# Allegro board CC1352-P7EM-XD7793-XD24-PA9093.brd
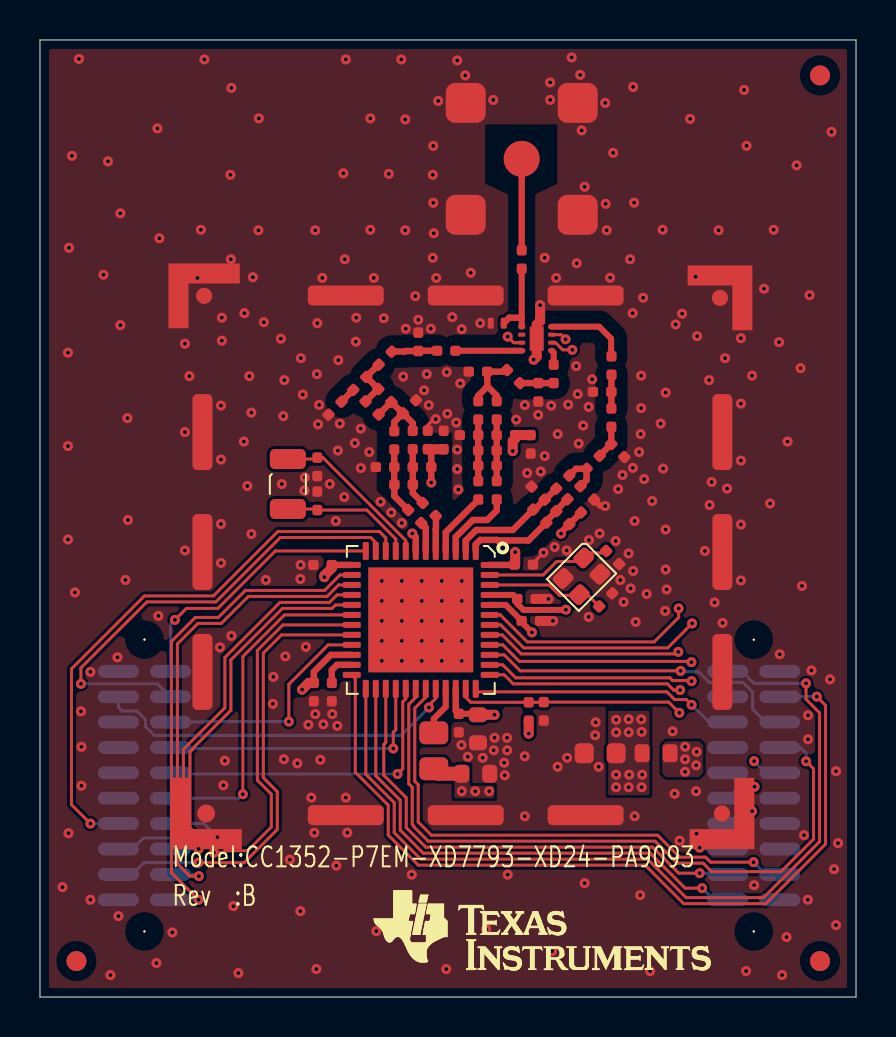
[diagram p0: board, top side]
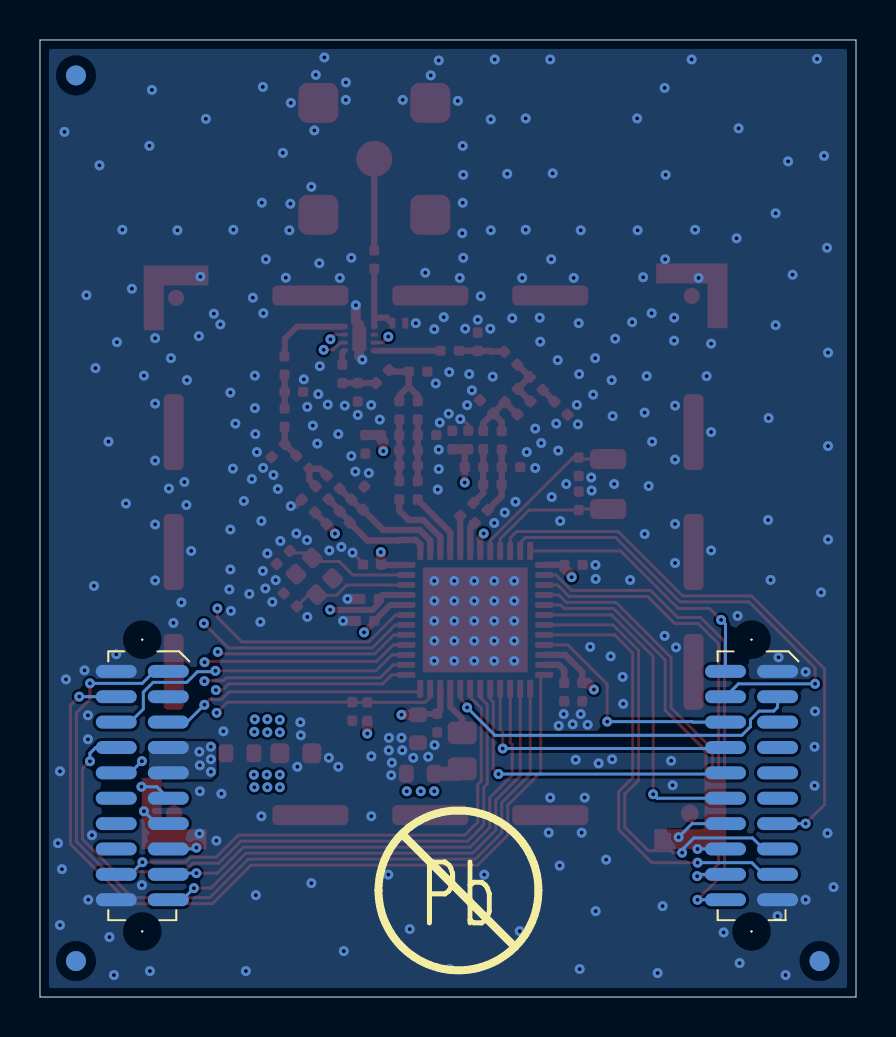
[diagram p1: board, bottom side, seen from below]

Outline 40.83 x 47.9 mm; copper layers: TOP, L2, L3, BOTTOM. Coordinates in mm from the lower left corner of the outline.
Outline path: 0,47.9 0,0 40.83,0 40.83,47.9 0,47.9

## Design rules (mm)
constraint set DEFAULT: min track width 0.15
net group RF SPACING: nets N485531 N485663 N485827 N485903 N512033 N512042 N512564 N513741 N516755 N517801 N517942 N518069 N553230 N583481 N2475926 N2476223 N2476600 N5175910

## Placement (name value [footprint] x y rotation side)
C1  22uF  [CAPC1608X100A2N#2]  28.83 12.2 180 top
C11  12pF  [CAPC1005X60B2N]  27.06 24.25 45 top
C12  1.1pF  [CAPC1005X60B2N]  26.39 24.91 45 top
C13  1pF  [CAPC1005X60B2N]  28.58 27.68 315 top
C14  1pF  [CAPC1005X60B2N]  28.58 30.29 180 top
C15  12pF  [CAPC1005X60B2N]  28.59 31.14 90 top
C21  1.1pF  [CAPC1005X60B2N]  25.25 24.89 135 top
C31  1.2pF  [CAPC1005X60B2N]  22.85 26.6 180 top
C32  100pF  [CAPC1005X60B2N]  24.55 28.12 270 top
C33  3pF  [CAPC1005X60B2N]  22.85 28.9 90 top
C34  2.7pF  [CAPC1005X60B2N]  22.37 31.3 180 top
C35  5.6pF  [CAPC1005X60B2N]  24.93 30.73 270 top
C37  100pF  [CAPC1005X60B2N]  25.7 31.65 270 top
C41  3pF  [CAPC1005X60B2N]  21.92 28.12 180 top
C51  82pF  [CAPC1005X60B2N]  19.4 28.35 270 top
C52  10nF  [CAPC1005X60B2N]  20.2 27.41 90 top
C53  2.4pF  [CAPC1005X60B2N]  18.65 27.41 90 top
C54  3.9pF  [CAPC1005X60B2N]  18.16 29.22 45 top
C55  0.7pF  [CAPC1005X60B2N]  16.94 29.16 135 top
C56  2.7pF  [CAPC1005X60B2N]  16.33 31.04 225 top
C57  2.7pF  [CAPC1005X60B2N]  18.93 32.33 90 top
C58  82pF  [CAPC1005X60B2N]  19.86 32.34 0 top
C61  2.4pF  [CAPC1005X60B2N]  16.8 26.52 0 top
C81  12pF  [CAPC1005X60B2N]  13.88 27 270 top
C91  12pF  [CAPC1005X60B2N]  13.88 24.38 90 top
C131  0.1uF  [CAPC1005X60B2N]  14.6 21.62 180 top
C221  0.1uF  [CAPC1005X60B2N]  13.7 15.72 270 top
C231  1uF  [CAPC1005X60B2N]  14.6 15.72 270 top
C331  22uF  [CAPC1608X100A2N]  21.1 11.17 0 top
C341  22uF  [CAPC1608X100A2N]  21.91 14.13 270 top
C342  0.1uF  [CAPC1005X60B2N]  20.95 14.17 270 top
C351  0.1uF  [CAPC1005X60B2N]  25.2 14.76 270 top
C441  0.1uF  [CAPC1005X60B2N]  24.1 18.83 0 top
C451  0.1uF  [CAPC1005X60B2N]  23.87 19.92 0 top
C461  7.5pF  [CAPC1005X60B2N]  27.98 19.55 45 top
C471  7.5pF  [CAPC1005X60B2N]  28.33 22.33 315 top
C481  0.1uF  [CAPC1005X60B2N]  23.74 21.64 0 top
C482  100pF  [CAPC1005X60B2N]  24.1 36.45 90 top
CR13  TPD1E0B04DPY  [SON65P100X60X45-2A2N]  22.55 33.72 0 top
FIDU1  FIDU_1MM  [FID100X115B]  1.83 1.8 0 top
FIDU2  FIDU_1MM  [FID100X115B]  39.02 1.8 0 top
FIDU3  FIDU_1MM  [FID100X115B]  39.02 46.12 0 top
FIDU4  FIDU_1MM  [FID100X115B]  1.83 1.8 180 bottom
FIDU5  FIDU_1MM  [FID100X115B]  39.02 1.8 180 bottom
FIDU6  FIDU_1MM  [FID100X115B]  39.02 46.12 180 bottom
FL1  BLM18HE152SN1  [FIL_BLM18HE152SN1DN]  30.12 12.2 0 top
J1  SMA-10V21-TGG  [HUSTSAN_SMA10V21TGGAN]  24.1 41.95 0 top
L11  15nH  [INDC1005X60D2N]  25.33 23.75 135 top
L12  2.4nH  [INDC1005X60D2N]  25.83 24.32 315 top
L13  1.5nH  [INDC1005X60D2N]  27.35 26.44 45 top
L14  2nH  [INDC1005X60D2N]  28.59 28.53 90 top
L21  2.4nH  [INDC1005X60D2N]  25.83 25.45 45 top
L31  3.9nH  [INDC1005X60D2N]  22.85 24.9 90 top
L32  22nH  [INDC1005X60D2N]  22.85 27.35 180 top
L33  10nH  [INDC1005X60D2N]  23.77 28.12 180 top
L34  7.5nH  [INDC1005X60D2N]  23.36 31.38 315 top
L41  3.9nH  [INDC1005X60D2N]  21.93 24.9 90 top
L42  10nH  [INDC1005X60D2N]  21.92 28.9 90 top
L51  1nH  [INDC1005X60D2N]  19.8 24.08 135 top
L52  27nH  [INDC1005X60D2N]  18.65 25.65 180 top
L53  12nH  [INDC1005X60B2N]  19.58 26.52 180 top
L54  4.3nH  [INDC1005X60B2N]  17.58 29.78 135 top
L55  2.5nH  [INDC1005X60B2N]  15.09 29.8 225 top
L56  4.7nH  [INDC1005X60B2N]  16.94 31.65 45 top
L61  1nH  [INDC1005X60D2N]  19.08 23.72 135 top
L62  12nH  [INDC1005X60B2N]  17.72 27.4 90 top
L331  6.8uH  [INDC2012X150A2N]  19.7 13.22 270 top
LBL1  TI_LOGO  [TI_LOGO_1]  17.67 5.35 0 top
LBL2  NON_COMPONENT_LABEL_8mm  [LABEL_PB-FREE_8MM_A2N]  24.1 1.12 180 bottom
NOREF  -  []  38.57 0 90 top
NOREF#2  -  []  0 42.03 0 top
P1  SFM-110-02-S-D-A-K  [SAMTEC_SFM11002AN]  3.92 16.3 0 bottom
P2  SFM-110-02-S-D-A-K  [SAMTEC_SFM11002AN]  34.4 16.3 0 bottom
R351  100k  [RESC1005X40B2N]  24.45 14.75 270 top
SC1  BMI-S-203-F  [MECH_BMIS203_A2N]  8.41 9.09 0 top
SC2  BMIS-203-C  [MECH_BMIS203C]  7.92 8.67 0 top
U1  CC1352P1F64TRGZ  [QFNFC50P700X700X100-49A2N]  21.8 22.33 180 top
U2  SKY13317-373  [SON40P150X150X50-9A2N]  24.1 33.55 270 top
Y1  32.768kHz  [XTAL_TZ1166C_A2N]  12.4 26.92 270 top
Y2  48MHz  [OSCCC200X160X50-4A2N]  27.2 21.97 225 top

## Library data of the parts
C1 C331 C341 = CAPACITOR: User Part Number: #PN; alternate symbols: (CAPC1608X100A2L,CAPC1608X100A2M)
C11-C15 C21 C31-C35 C37 C41 C51-C58 C61 C81 C91 C131 C221 C231 C342 C351 C441 C451 C461 C471 C481 C482 = CAPACITOR: User Part Number: #PN
CR13 = DIODE_TVS_BIDIR_S: User Part Number: #PN
FIDU1-FIDU6 = FIDMARK
FL1 = FILTER_2PIN: alternate symbols: (FIL_BLM18HE152SN1DL,FIL_BLM18HE152SN1DM)
J1 = CONN_COAX_1+4: alternate symbols: (HUSTSAN_SMA10V21TGGL,HUSTSAN_SMA10V21TGGM)
L11 L31 L33 L41 L42 L51 L61 = INDUCTOR_HOR_1_2: User Part Number: #PN; alternate symbols: (INDC1005X60C2L,INDC1005X60C2M)
L12-L14 L21 L32 L34 L52 = INDUCTOR_HOR_1_2: User Part Number: #PN
L53-L56 L62 = INDUCTOR: User Part Number: #PN; alternate symbols: (INDC1005X60A2L,INDC1005X60A2M)
L331 = INDUCTOR: User Part Number: #PN; alternate symbols: (INDC2012X150A2L,INDC2012X150A2M)
LBL1 = TI_LOGO_V1
LBL2 = LABEL_Pb-free_V1: User Part Number: #PN
P1 P2 = CONN_HEADER_2X10_P_S: alternate symbols: (SAMTEC_SFM11002AL,SAMTEC_SFM11002AM)
R351 = RESISTOR: User Part Number: #PN
SC1 = SHIELD_COVER_BMIS-203
SC2 = SHIELD_COVER: User Part Number: #PN
U1 = IC_RF_CC1352P1F64_QFN48: User Part Number: #PN; alternate symbols: (QFNFC50P700X700X100-49A2L,QFNFC50P700X700X100-49A2M)
U2 = IC_RF_SKY13317-373LF_MLP8: User Part Number: #PN
Y1 = XTAL: User Part Number: #PN; alternate symbols: (XTAL_TZ1166C_A2L,XTAL_TZ1166C_A2M)
Y2 = XTAL_4_V3: User Part Number: #PN; alternate symbols: (OSCCC200X160X50-4A2L,OSCCC200X160X50-4A2M)

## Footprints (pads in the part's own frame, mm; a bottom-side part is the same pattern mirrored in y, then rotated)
CAPC1005X60B2N
  custom 0.125x0.125 smd: 1(0,0) 2(0.924,0)
CAPC1608X100A2N
  custom 0.188x0.188 smd: 1(0,0) 2(1.4,0)
CAPC1608X100A2N#2
  custom 0.237x0.237 smd: 1(0,0) 2(1.6,0)
FID100X115B
  round 1 smd: 1(0,0)
FIL_BLM18HE152SN1DN
  custom 0.188x0.188 smd: 1(0,0) 2(1.4,0)
HUSTSAN_SMA10V21TGGAN
  round 1.801 smd: 1(0,0)
  custom 0.5x0.5 smd: 2(-2.8,-2.8) 3(2.8,-2.8) 4(2.8,2.8) 5(-2.8,2.8)
INDC1005X60B2N
  custom 0.125x0.125 smd: 1(0,0) 2(0.924,0)
INDC1005X60D2N
  custom 0.125x0.125 smd: 1(0,0) 2(0.924,0)
INDC2012X150A2N
  custom 0.287x0.287 smd: 1(0,0) 2(1.8,0)
MECH_BMIS203_A2N
  custom 0.892x0.892 smd: 1(-0.1,0.1)
  custom 0.25x0.25 smd: 2(6.885,0.015) 3(12.885,0.015) 4(18.885,0.015) 6(25.725,7.185) 7(25.725,13.185) 8(25.725,19.185) 10(18.885,26.025) 11(12.885,26.025) 12(6.885,26.025) 14(-0.285,19.185) 15(-0.285,13.185) 16(-0.285,7.185)
  custom 0.81x0.81 smd: 5(25.705,0.1) 9(25.605,25.905) 13(-0.2,26.005)
OSCCC200X160X50-4A2N
  custom 0.2x0.2 smd: 1(0,0) 2(1.45,0) 3(1.45,1.15) 4(0,1.15)
QFNFC50P700X700X100-49A2N
  custom 0.075x0.075 smd: 1(0,0) 2(0.5,0) 3(1,0) 4(1.5,0) 5(2,0) 6(2.5,0) 7(3,0) 8(3.5,0) 9(4,0) 10(4.5,0) 11(5,0) 12(5.5,0) 13(6.2,0.7) 14(6.2,1.2) 15(6.2,1.7) 16(6.2,2.2) 17(6.2,2.7) 18(6.2,3.2) 19(6.2,3.7) 20(6.2,4.2) 21(6.2,4.7) 22(6.2,5.2) 23(6.2,5.7) 24(6.2,6.2) 25(5.5,6.9) 26(5,6.9) 27(4.5,6.9) 28(4,6.9) 29(3.5,6.9) 30(3,6.9) 31(2.5,6.9) 32(2,6.9) 33(1.5,6.9) 34(1,6.9) 35(0.5,6.9) 36(0,6.9) 37(-0.7,6.2) 38(-0.7,5.7) 39(-0.7,5.2) 40(-0.7,4.7) 41(-0.7,4.2) 42(-0.7,3.7) 43(-0.7,3.2) 44(-0.7,2.7) 45(-0.7,2.2) 46(-0.7,1.7) 47(-0.7,1.2) 48(-0.7,0.7)
  rect 5.25x5.25 smd: 49(2.75,3.45)
RESC1005X40B2N
  custom 0.125x0.125 smd: 1(0,0) 2(0.924,0)
SAMTEC_SFM11002AN
  round 0.099 hole 1.501 unplated: (1.302,-1.588) (1.302,13.017)
  oval 2.05x0.65 smd: 1(0,0) 2(2.604,0) 3(0,1.27) 4(2.604,1.27) 5(0,2.54) 6(2.604,2.54) 7(0,3.81) 8(2.604,3.81) 9(0,5.08) 10(2.604,5.08) 11(0,6.35) 12(2.604,6.35) 13(0,7.62) 14(2.604,7.62) 15(0,8.89) 16(2.604,8.89) 17(0,10.16) 18(2.604,10.16) 19(0,11.43) 20(2.604,11.43)
SON40P150X150X50-9A2N
  custom 0.05x0.05 smd: 1(0,0) 2(0.4,0) 3(0.8,0) 4(1.2,0) 5(1.2,1.5) 6(0.8,1.5) 7(0.4,1.5) 8(0,1.5)
  rect 1.2x0.7 smd: 9(0.6,0.75)
SON65P100X60X45-2A2N
  custom 0.075x0.075 smd: 1(0,0) 2(0.65,0)
XTAL_TZ1166C_A2N
  custom 0.25x0.25 smd: 1(0,0) 2(2.5,0)

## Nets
GND: C1.2 C11.2 C13.2 C14.2 C21.2 C32.2 C34.2 C35.2 C41.2 C51.1 C52.2 C54.2 C57.2 C61.1 C81.2 C91.2 C131.2 C221.2 C231.2 C331.2 C341.2 C342.2 C351.2 C441.2 C451.2 C461.2 C471.2 C481.2 CR13.1 J1.2 J1.3 J1.4 J1.5 L55.2 P1.1 P1.19 P2.2 P2.20 SC1.1 SC1.2 SC1.3 SC1.4 SC1.5 SC1.6 SC1.7 SC1.8 SC1.9(GND#9) SC1.10 SC1.11 SC1.12 SC1.13 SC1.14 SC1.15 SC1.16 U1.49 U2.9 Y2.2 Y2.4(GND#4)
VDD_EB: FL1.2 P2.7 P2.9
VDDR: C331.1 C451.1 C481.1 L331.2 U1.45 U1.48
VDDS: C1.1 C51.2 C52.1 C131.1 C221.1 C341.1 C342.1 C441.1 FL1.1 L53.1 R351.2 U1.13 U1.22 U1.34 U1.44
DCDC_SW: L331.1 U1.33
DIO_5: P1.13 U1.10
DIO_6: P1.4 U1.11
DIO_7: P1.2 U1.12
DIO_8: P1.20 U1.14
DIO_9: P1.18 U1.15(DIO_9)
DIO_10: P1.16 U1.16
DIO_11: P1.14 U1.17
DIO_12: P1.12 U1.18
DIO_13: P1.15 U1.19
DIO_14: P1.17 U1.20
DIO_15: P1.6 U1.21
DIO_16 / JTAG TDO: P2.19 U1.26
DIO_17 / JTAG TDI: P2.17 U1.27
DIO_18: P1.8 U1.28
DIO_19: P1.10 U1.29
DIO_20: P2.8 U1.30
DIO_21: P2.18 U1.31
DIO_22: P1.3 U1.32
DIO_23: P2.5 U1.36
DIO_24: P2.10 U1.37
DIO_25: P2.11 U1.38
DIO_26: P2.6 U1.39
DIO_27: P2.13 U1.40
DIO_28: U1.41 U2.7(V3)
DIO_29: U1.42 U2.3
DIO_30: U1.43 U2.6
JTAG_TCK: P2.1 U1.25
JTAG_TMS: P2.4 U1.24
NRESET: C351.1 P2.15 R351.1 U1.35
RX_TX: C11.1 C32.1 L12.2 L33.1 U1.7
N485531: C37.1 U2.5
N485533: C482.2 J1.1
N485663: C33.2 C34.1 L34.1 L42.2
N485699: C231.1 U1.23
N485701: C81.1 U1.8 Y1.1
N485707: C91.1 U1.9 Y1.2
N485827: C35.1 C37.2 L34.2
N485903: C31.1 C33.1 L31.2 L32.1 L33.2
N501959: C471.1 U1.47 Y2.1
N501977: C461.1 U1.46 Y2.3
N512033: C12.2 L13.1 L21.2
N512042: C13.1 L13.2 L14.1
N512564: C15.2 U2.8
N513741: C21.1 L11.2 L21.1 U1.2
N516755: C31.2 C41.1 L32.2 L41.2 L42.1
N517773: C53.1 L51.2 L52.1 L53.2
N517777: C61.2 L52.2 L61.2 L62.1
N517801: C53.2 C54.1 C55.1 L54.1 L62.2
N517942: C55.2 C56.1 L54.2 L56.1
N518069: C57.1 C58.1 L56.2
N553230: C14.1 C15.1 L14.2
N561899: L61.1 U1.6
N583447: C482.1 CR13.2 U2.1
N583481: C58.2 U2.4
N2475876: L51.1 U1.5
N2475926: L41.1 U1.4
N2476223: L31.1 U1.3
N2476600: C12.1 L11.1 L12.1 U1.1
N5175910: C56.2 L55.1

Pads without a net: FIDU1 1; FIDU2 1; FIDU3 1; FIDU4 1; FIDU5 1; FIDU6 1; P1 5 7 9 11; P2 3 12 14 16; U2 2

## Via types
v1: diameter 0.5, hole 0.2, TOP to BOTTOM, 395 vias

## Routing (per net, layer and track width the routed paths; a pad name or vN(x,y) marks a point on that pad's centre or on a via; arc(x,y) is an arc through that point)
GND: length 6.5
  TOP w0.15: C481.2 24.66,21.72 v1(25.19,22.24) ; 19.83,28.92 v1(19.8,28.92) 19.7,28.92 19.4,28.62 C51.1
  TOP w0.3: v1(28.28,24.57) 28.05,24.57 27.72,24.9
  TOP w0.5: C451.2 v1(25.44,19.92) ; v1(25.02,34.62) 25.02,33.82 24.85,33.65 U2.9 24.85,32.05 v1(24.7,31.9) ; C441.2 v1(25.66,18.83) ; 13.23,25.35 v1(13.23,25.35)
  vias: v1(1.12,5.5) v1(1.45,37.5) v1(1.4,32.25) v1(1.4,27.58) v1(1.4,22.9) v1(1.42,8.2) v1(1.6,42.1) v1(1.75,20.25) v1(1.95,46.95) v1(2.05,14.3) v1(2.08,12.52) v1(2.08,10.58) v1(2.52,16.27) v1(2.52,4.87) v1(3.17,36.15) v1(3.4,41.83) v1(3.52,1.1) v1(3.88,17) v1(3.92,4.05) v1(4.02,39.23) v1(4.02,33.62) v1(4.27,20.88) v1(4.38,28.97) v1(4.4,23.88) v1(5.83,1.7) v1(5.88,43.48) v1(5.97,37.98) v1(5.92,19.08) v1(6.62,3.23) v1(7.25,32.7) v1(7.25,28.27) v1(7.25,22.35) v1(7.47,31.08) v1(7.88,35.99) v1(8.05,38.4) v1(8.22,46.92) v1(9.05,29.6) v1(9.05,26.9) v1(9.05,23.67) v1(9.05,21.72) v1(9,17.5) v1(9.1,34) v1(9.1,32.85) v1(9.17,10.6) v1(9.25,11.83) v1(9.52,41.15) v1(9.55,36.92) v1(9.58,45.5) v1(9.58,18.08) v1(9.67,4.55) v1(9.92,1.2) v1(10.22,34.22) v1(10.2,27.8) v1(10.47,31.08) v1(10.38,25.58) v1(10.65,36.02) v1(10.58,29.25) v1(10.58,23.17) v1(10.95,43.98) v1(10.93,38.37) v1(11.2,33.77) v1(11.3,20.88) v1(11.65,14.67) v1(11.67,16.02) v1(12.05,32.95) v1(12.17,29.08) v1(12.1,25.67) v1(12.22,30.88) v1(12.27,17.05) v1(12.2,11.9) v1(12.5,6.88) v1(12.88,11.69) v1(13.05,31.97) v1(13.04,21.62) v1(13.02,20.92) v1(13.02,4.3) v1(13.15,30.15) v1(13.25,26) v1(13.3,17.52) v1(13.42,13.62) v1(13.58,9.98) v1(13.77,38.37) v1(13.77,14.16) v1(13.72,8.23) v1(13.85,31.17) v1(13.83,1.4) v1(13.88,33.72) v1(13.97,29.63) v1(13.91,28.66) v1(14.02,11.88) v1(14.12,35.99) v1(14.17,13.65) v1(14.5,25.67) v1(14.62,14.16) v1(14.8,23.83) v1(14.83,6.58) v1(14.92,31.88) v1(14.9,27.35) v1(14.88,13.58) v1(15,28.7) v1(15.17,41.23) v1(15.25,36.92) v1(15.22,25.02) v1(15.3,46.92) v1(15.3,9.98) v1(15.38,8.23) v1(15.75,27.72) v1(15.82,34) v1(15.8,32.8) v1(16.05,28.45) v1(16.05,26.47) v1(16.47,27.27) v1(16.53,43.98) v1(16.53,38.4) v1(16.7,35.99) v1(16.83,3.3) v1(17.04,24.79) v1(17.1,20.83) v1(17.1,19.83) v1(17.1,18.83) v1(17.1,17.83) v1(17.1,16.83) v1(17.2,33.97) v1(17.45,41.2) v1(17.57,24.25) v1(18.08,46.92) v1(18.17,31.05) v1(18.1,23.72) v1(18.1,20.83) v1(18.1,19.83) v1(18.1,18.83) v1(18.1,17.83) v1(18.1,16.83) v1(18.27,43.92) v1(18.27,38.37) v1(18.3,33.45) v1(18.6,6.12) v1(18.77,35.08) v1(18.92,33.9) v1(19.1,20.83) v1(19.1,19.83) v1(19.1,18.83) v1(19.1,17.83) v1(19.1,16.83) v1(19.22,30.37) v1(19.35,31.17) v1(19.45,29.62) v1(19.55,33.45) v1(19.65,41.15) v1(19.65,37) v1(19.67,42.6) v1(19.67,39.75) v1(19.7,38.23) v1(19.83,35.99) v1(19.92,44.85) v1(20.1,20.83) v1(20.1,19.83) v1(20.1,18.83) v1(20.1,17.83) v1(20.1,16.83) v1(20.35,31.27) v1(20.33,1.4) v1(20.38,29.19) v1(20.62,34.02) v1(20.82,28.75) v1(20.88,46.87) v1(20.88,27.4) v1(20.88,26.42) v1(20.92,25.4) v1(21.02,30.71) v1(21.1,33.42) v1(21.1,20.83) v1(21.1,19.83) v1(21.1,18.83) v1(21.1,17.83) v1(21.1,16.83) v1(21.09,12.61) v1(21.27,46.13) v1(21.4,12.02) v1(21.55,36.25) v1(22.02,33.72) v1(22.15,11.97) v1(22.33,3.4) v1(22.68,44.9) v1(22.74,12.98) v1(22.7,12.35) v1(23.22,11.73) v1(23.25,11.1) v1(23.37,12.97) v1(23.38,12.35) v1(23.4,6.12) v1(23.83,28.9) v1(24.25,29.62) v1(24.25,12.05) v1(24.25,9.05) v1(24.37,26.22) v1(24.92,29.13) v1(25.05,26.3) v1(25.25,37) v1(25.25,27.08) v1(25.52,45.77) v1(25.52,44.9) v1(25.58,29.6) v1(25.62,2.3) v1(25.75,22.53) v1(25.83,35.99) v1(25.9,28.17) v1(25.9,11.52) v1(26.35,22.35) v1(26.37,11.97) v1(26.42,29.65) v1(26.6,47.02) v1(26.85,36.73) v1(26.83,31.58) v1(26.9,30.17) v1(26.95,27.7) v1(27.02,46.15) v1(27.1,43.37) v1(27.17,28.6) v1(27.25,40.55) v1(27.25,5.7) v1(27.45,29.54) v1(27.47,22.87) v1(27.45,19.02) v1(27.62,30.91) v1(27.77,13.1) v1(27.8,13.75) v1(27.95,11.52) v1(28,23.2) v1(28.28,44.75) v1(28.3,39.7) v1(28.35,38.37) v1(28.52,36) v1(28.67,42.25) v1(28.8,22.83) v1(28.92,25.42) v1(29.03,20.87) v1(29.14,26.13) v1(29.2,19.77) v1(29.45,22.2) v1(29.52,36.92) v1(29.55,20.45) v1(29.65,34.22) v1(29.66,26.48) v1(29.67,45.55) v1(29.73,39.76) v1(29.75,23.83) v1(29.67,21.33) v1(29.75,9.05) v1(29.8,18.77) v1(30.05,28.17) v1(29.98,27.27) v1(30.02,5.1) v1(30.17,35) v1(30.08,31.1) v1(30.08,29.47) v1(30.23,25.92) v1(30.35,20.17) v1(30.52,1.3) v1(30.62,24.83) v1(31.05,28.7) v1(31.15,38.4) v1(31.17,26.45) v1(31.27,19.33) v1(31.3,30.25) v1(31.3,23.4) v1(31.3,21.4) v1(31.35,20.4) v1(31.65,13.3) v1(31.75,10.17) v1(31.8,33.66) v1(32,7.83) v1(32.12,34.2) v1(32.52,43.95) v1(32.8,36.05) v1(32.87,33.08) v1(32.83,10.3) v1(32.85,8.17) v1(33.26,22.33) v1(33.48,30.88) v1(33.5,24.62) v1(33.6,25.77) v1(33.75,19.75) v1(33.95,38.37) v1(34.15,18.72) v1(34.27,31.97) v1(34.37,25.45) v1(35.06,32.97) v1(35.06,29.7) v1(35.06,26.85) v1(35.06,23.65) v1(35.06,20.85) v1(35.23,45.4) v1(35.35,42.6) v1(35.33,1.3) v1(35.62,31.1) v1(35.73,5.6) v1(36.23,35.45) v1(36.52,24.7) v1(36.7,38.4) v1(36.98,32.77) v1(37.01,17.15) v1(37.12,1.1) v1(37.35,3) v1(37.4,27.8) v1(37.85,41.62) v1(38.05,31.47) v1(38.12,20.58) v1(38.23,8.1) v1(38.42,14.1) v1(38.42,12.9) v1(38.41,4.87) v1(38.5,35.12) v1(38.59,16.35) v1(39.52,15.9) v1(39.6,43.3) v1(39.73,6.4) v1(39.83,11.3) v1(39.83,3.6) v1(39.92,7.7)
VDD_EB:
  vias: v1(32.27,11.27) v1(32.28,12.53) v1(32.28,11.9) v1(32.85,12.27) v1(32.83,11.6)
VDDR: length 7.7
  TOP w0.3: v1(26.31,19.38) 26.3,19.38 24.19,19.38 23.87,19.69 C451.1 23.67,20.12 U1.45
  TOP w0.32: U1.48 23.73,21.62 C481.1
  TOP w0.5: C481.1 23.77,21.67 v1(23.77,22.27)
  TOP w0.7: L331.2 19.95,11.17 C331.1
  vias: v1(21.1,10.3) v1(21.77,10.3) v1(22.48,10.3)
VDDS: length 14.3
  TOP w0.3: C341.1 21.86,14.17 C342.1 ; U1.44 23.3,19.62 C441.1 24.1,18.76 v1(24.61,18.25)
  TOP w0.32: C342.1 20.8,14.33 U1.34 ; 19.41,27.41 19.58,27.25 L53.1 v1(19.58,25.75) ; U1.22 14.55,17.12 13.7,16.27 C221.1 ; U1.13 C131.1
  TOP w0.5: C51.2 19.41,27.41 C52.1 ; C341.1 v1(22.74,14.13) ; v1(13.11,15.39) 13.45,15.72 C221.1 ; v1(14.23,21.01) 14.23,21.1 14.6,21.47 C131.1 ; R351.2 v1(24.45,13.19)
  vias: v1(28.83,13.88) v1(28.83,13.25) v1(28.83,11.13) v1(28.82,10.5) v1(29.45,13.9) v1(29.45,13.25) v1(29.45,10.5) v1(29.48,11.13) v1(30.08,13.9) v1(30.1,13.27) v1(30.13,11.13) v1(30.1,10.5)
DCDC_SW: length 2.4
  TOP w0.3: U1.33 20.3,14.52 19.7,13.92 L331.1
DIO_5: length 28.9
  TOP w0.15: v1(2.52,8.68) 1.58,9.63 1.58,16.42 5.23,20.08 8.67,20.08 11.9,23.3 16.98,23.3 17.3,22.98 U1.10
  BOTTOM w0.15: P1.13 v1(2.52,8.68)
DIO_6: length 23.5
  TOP w0.15: U1.11 16.8,22.74 16.54,23 12.02,23 8.8,19.77 5.35,19.77 2.05,16.47 v1(2.05,15.68)
  BOTTOM w0.15: v1(2.05,15.67) 5.88,15.67 P1.4
DIO_7: length 13.6
  TOP w0.15: U1.12 11.77,22.33 8.9,19.45 7.33,19.45 v1(6.75,18.88)
  BOTTOM w0.15: v1(6.75,18.88) 6.53,18.65 P1.2
DIO_8: length 25.3
  TOP w0.15: U1.14 15.01,21.12 14.23,20.35 10.28,20.35 8.92,19 7.77,19 6.58,17.8 6.58,6.22 v1(7.93,4.87)
  BOTTOM w0.15: v1(7.93,4.87) 7.78,4.87 7.78,4.87 P1.20
DIO_9: length 23.7
  TOP w0.15: U1.15 14.94,20.62 14.36,20.05 10.42,20.05 9.07,18.7 7.9,18.7 6.88,17.67 6.88,6.67 7.5,6.05 v1(7.95,6.05)
  BOTTOM w0.15: P1.18 7.86,6.14 v1(7.95,6.05)
DIO_10: length 19.8
  TOP w0.15: v1(7.93,7.41) 7.17,8.17 7.17,12.4 9.25,14.47 9.25,16.99 12.01,19.75 14.48,19.75 14.86,20.12 U1.16
  BOTTOM w0.15: v1(7.93,7.41) P1.16
DIO_11: length 20.6
  TOP w0.15: v1(8.88,8) 7.97,8 7.5,8.47 7.5,12.27 7.65,12.41 7.65,12.45 9.55,14.35 9.55,16.87 12.13,19.45 14.61,19.45 14.78,19.62 U1.17
  BOTTOM w0.15: P1.14 8.2,8.68 v1(8.88,8)
DIO_12: length 16.9
  TOP w0.15: v1(10.15,10.15) 10.15,17.04 12.23,19.12 U1.18
  BOTTOM w0.15: P1.12 9.95,9.95 v1(10.15,10.15)
DIO_13: length 23.2
  TOP w0.15: U1.19 12.16,18.62 10.88,17.34 10.88,10.85 11.57,10.15 11.57,8.51 10.39,7.33 9.25,7.33 9.15,7.22 v1(8.7,7.22)
  BOTTOM w0.15: v1(8.7,7.22) 8.7,7.38 8.11,7.96 5.17,7.96 4.62,7.41 P1.15
DIO_14: length 22.8
  TOP w0.15: v1(7.92,6.72) 10.21,6.72 11.87,8.38 11.87,10.28 11.17,10.98 11.17,17.22 12.08,18.12 U1.20
  BOTTOM w0.15: v1(7.92,6.72) 5.21,6.72 4.62,6.14 P1.17
DIO_15: length 11.8
  TOP w0.15: U1.21 14.42,17.62 12.45,15.66 v1(12.45,13.78)
  BOTTOM w0.15: v1(12.45,13.78) 8.2,13.78 8.17,13.76 P1.6
DIO_16 / JTAG TDO: length 25.4
  TOP w0.15: v1(33.12,5.45) 32.27,5.45 30.52,7.2 19.18,7.2 18.02,8.35 18.02,9.85 16.8,11.08 U1.26
  BOTTOM w0.15: v1(33.12,5.45) 33.7,4.87 P2.19
DIO_17 / JTAG TDI: length 24.5
  TOP w0.15: U1.27 17.3,12.74 17.2,12.64 17.2,11.1 18.32,9.98 18.32,8.48 19.3,7.5 30.65,7.5 31.95,6.2 v1(33,6.2)
  BOTTOM w0.15: v1(33,6.2) 33.64,6.2 33.7,6.14 P2.17
DIO_18: length 14.2
  TOP w0.15: v1(17.67,12.44) 17.67,13.25 17.8,13.38 U1.28
  BOTTOM w0.15: v1(17.67,12.44) 6.58,12.44 P1.8
DIO_19: length 15.8
  TOP w0.15: v1(17.89,11.16) 18.15,11.42 18.15,14.77 18.3,14.92 U1.29
  BOTTOM w0.15: v1(17.89,11.16) 6.59,11.16 P1.10
DIO_20: length 34.6
  TOP w0.15: v1(38.33,11.8) 38.7,11.42 38.7,7.9 37.07,6.27 33.6,6.27 33.17,6.7 31.87,6.7 30.77,7.8 19.43,7.8 18.7,8.53 18.7,8.56 18.62,8.63 18.62,10.5 18.45,10.67 18.45,14.65 18.8,15 U1.30
  BOTTOM w0.15: v1(38.33,11.8) 38.33,12.2 38.04,12.49 P2.8
DIO_21: length 26.1
  TOP w0.15: U1.31 19.3,15.01 18.75,14.46 18.75,10.8 18.92,10.63 18.92,8.76 19.58,8.1 30.9,8.1 32,7 33.3,7 33.55,6.75 v1(35.7,6.75)
  BOTTOM w0.15: P2.18 36.31,6.14 v1(35.7,6.75)
DIO_22: length 18.5
  TOP w0.15: v1(19.46,14.49) 19.46,14.6 19.8,14.94 U1.32
  BOTTOM w0.15: P1.3 3.92,14.5 4.12,14.31 4.85,14.31 5.28,13.88 5.28,13.53 5.71,13.1 18.07,13.1 v1(19.46,14.49)
DIO_23: length 13.3
  TOP w0.15: U1.36 21.95,15.27 31.36,15.27 31.75,14.89 32.34,14.89 v1(32.6,14.62)
  BOTTOM w0.15: P2.5 33.46,13.76 v1(32.6,14.62)
DIO_24: length 16.8
  TOP w0.15: U1.37 23.23,16.12 23.68,15.67 31.39,15.67 31.7,15.36 v1(32.02,15.36)
  L3 w0.15: v1(32.02,15.36) 32.05,15.33 32.56,15.33 35.2,12.7 35.2,12.33 v1(35.73,11.8)
  BOTTOM w0.15: P2.10 36.31,11.22 v1(35.73,11.8)
DIO_25: length 19
  TOP w0.15: v1(32.6,15.81) 32.57,15.84 31.65,15.84 31.51,15.97 23.8,15.97 23.15,16.62 U1.38
  L3 w0.15: v1(32.6,15.81) 36.2,12.21 36.2,10.97 v1(35.75,10.52)
  BOTTOM w0.15: v1(35.75,10.52) 34.98,10.52 P2.11
DIO_26: length 16.4
  TOP w0.15: U1.39 23.23,17.12 24.03,16.33 v1(32.05,16.33)
  BOTTOM w0.15: v1(32.05,16.33) 32.09,16.28 32.94,16.28 33.48,15.75 35.16,15.75 35.65,15.26 35.65,14.41 36.31,13.76 P2.6
DIO_27: length 21.4
  TOP w0.15: v1(32.59,16.76) 32.55,16.8 23.98,16.8 23.15,17.62 U1.40
  L3 w0.15: v1(32.59,16.76) 36.5,12.85 36.5,10.17 v1(35.62,9.3)
  BOTTOM w0.15: P2.13 35.01,8.68 v1(35.62,9.3)
DIO_28: length 31.1
  TOP w0.15: v1(31.93,17.27) 31.83,17.17 24.07,17.17 23.12,18.12 U1.41 ; U2.7 26.07,33.15 v1(26.3,32.92)
  L3 w0.15: v1(31.93,17.27) 31.93,18.71 32.42,19.2 32.42,19.65 32.25,19.82 32.25,30.4 29.73,32.92 v1(26.3,32.92)
DIO_29: length 34.5
  TOP w0.15: U2.3 23.7,32.75 v1(23.4,33.05) ; v1(32.62,18.7) 32.3,18.38 32.3,18.38 31.4,17.47 24.2,17.47 23.05,18.62 U1.42
  L3 w0.15: v1(23.4,33.05) 23.74,33.39 29.68,33.39 32.55,30.52 32.55,19.95 32.95,19.55 32.95,19.02 v1(32.62,18.7)
DIO_30: length 29.2
  TOP w0.15: U2.6 25.79,32.75 26.15,32.39 v1(26.63,32.39) ; U1.43 23.03,19.12 24.38,17.77 30.73,17.77 31.95,19 v1(31.95,19.45)
  L3 w0.15: v1(26.63,32.39) 29.83,32.39 31.95,30.27 v1(31.95,19.45)
JTAG_TCK: length 43.9
  TOP w0.15: v1(38.33,15.7) 38.33,14.9 39,14.22 39,7.78 36.2,4.97 32.33,4.97 30.4,6.9 19.05,6.9 17.72,8.23 17.72,9.73 16.3,11.15 U1.25
  BOTTOM w0.15: v1(38.33,15.7) 35.7,15.7 35.11,16.3 P2.1
JTAG_TMS: length 42.7
  TOP w0.15: U1.24 15.77,15.95 15.77,11.25 17.42,9.6 17.42,8.1 18.93,6.6 30.27,6.6 32.2,4.67 36.32,4.67 39.3,7.65 39.3,14.6 v1(38.86,15.04)
  BOTTOM w0.15: P2.4 38.4,15.03 38.41,15.04 v1(38.86,15.04)
NRESET: length 20.3
  TOP w0.15: v1(31.99,14.22) 31.45,14.76 C351.1 25.19,14.75 R351.1 21.56,14.75 21.3,15.01 U1.35
  L3 w0.15: v1(33,7.47) 33.33,7.8 33.33,12.88 v1(31.99,14.22)
  BOTTOM w0.15: v1(33,7.47) 33.07,7.41 P2.15
RX_TX: length 16.1
  TOP w0.32: C11.1 L12.2 26.1,23.28 26.1,23.22 v1(26.07,23.19) ; v1(18.62,23.2) 18.8,23.02 U1.7
  TOP w0.5: C32.1 L33.1 23.77,27.95 23.65,27.83 v1(23.65,27.33)
  L3 w0.5: v1(23.65,27.33) 23.65,24.44 22.4,23.19 ; 22.4,23.19 22.39,23.19 19.26,23.19 19.25,23.2 v1(18.62,23.2) ; 22.4,23.19 v1(26.07,23.19)
N485531: length 0.7
  TOP w0.3: U2.5 25.7,32.25 C37.1
N485533: length 4.6
  TOP w0.32: C482.2 J1.1
N485663: length 3.6
  TOP w0.32: 22.33,30.5 22.37,30.55 C34.1 23.28,31.3 L34.1 ; 22.33,30.5 21.92,30.1 L42.2 ; 22.33,30.5 22.45,30.5 22.85,30.1 C33.2
N485699: length 1.7
  TOP w0.32: C231.1 14.6,16.36 14.86,16.62 U1.23
N485701: length 8.2
  TOP w0.15: U1.8 18.3,22.85 14.15,27 C81.1 13.8,26.92 Y1.1
N485707: length 6.6
  TOP w0.15: Y1.2 13.83,24.42 C91.1 16.35,24.38 17.8,22.92 U1.9
N485827: length 1.7
  TOP w0.15: 24.02,30.73 L34.2 ; 24.93,30.73 C35.1
  TOP w0.32: C37.2 24.93,30.73 ; C35.1 24.02,30.73
N485903: length 3.1
  TOP w0.15: 22.85,26.6 C31.1 ; 22.85,28.12 L33.2
  TOP w0.32: L31.2 C31.1 ; 22.85,28.12 L32.1 22.85,26.6 ; L33.2 C33.1
N501959: length 6.3
  TOP w0.15: U1.47 25.17,21.12 25.85,21.8 27.02,21.8 Y2.1 27.45,22.22 28.23,22.22 C471.1
N501977: length 5.9
  TOP w0.15: U1.46 25.48,20.62 26,20.1 26.95,20.1 26.99,20.14 27.39,20.14 C461.1
N512033: length 2
  TOP w0.32: C12.2 27.35,25.87 L13.1 26.81,26.44 26.48,26.1
N512042: length 1.7
  TOP w0.32: L13.2 28,27.1 C13.1 28.58,28.53 L14.1
N512564: length 4.1
  TOP w0.3: C15.2 28.58,32.08 28.58,32.95 27.98,33.55 U2.8
N513741: length 6.1
  TOP w0.32: L21.1 25.27,24.89 C21.1 24.75,24.4 24.68,24.4 23.65,23.38 21.83,23.38 21.3,22.85 U1.2
N516755: length 3.1
  TOP w0.15: 21.92,26.6 C31.2 21.93,26.6
  TOP w0.32: L41.2 21.93,26.6 ; L42.1 C41.1 L32.2 21.92,26.6
N517773: length 2.9
  TOP w0.32: L51.2 18.65,25.22 L52.1 18.65,26.52 L53.2 18.65,26.53 C53.1
N517777: length 3.3
  TOP w0.32: L61.2 17.73,25.07 L52.2 17.72,25.65 C61.2 17.72,26.53 L62.1
N517801: length 3.9
  TOP w0.32: C54.1 18.65,28.73 C53.2 ; C54.1 17.72,28.78 L62.2 ; C54.1 18.14,29.22 L54.1 17.57,29.78 C55.1
N517942: length 2.6
  TOP w0.32: L56.1 16.94,31.65 C56.1 L54.2 16.91,30.43 16.29,29.81
N518069: length 2.3
  TOP w0.32: C58.1 18.94,32.34 C57.1 18.27,32.33 18.25,32.31 17.61,32.31 L56.2
N553230: length 1.7
  TOP w0.32: C15.1 C14.1 28.59,30.28 L14.2
N561899: length 1.5
  TOP w0.32: U1.6 19.3,23.5 L61.1
N583447: length 3.9
  TOP w0.3: C482.1 U2.1
  TOP w0.32: CR13.2 23.48,34 24.1,34
N583481: length 3.3
  TOP w0.15: 24.09,32.34 U2.4
  TOP w0.3: C58.2 24.09,32.34
N2475876: length 1.8
  TOP w0.32: U1.5 19.8,23.42 19.81,23.42 19.81,24.07 L51.1
N2475926: length 3.2
  TOP w0.32: L41.1 21.93,24.89 20.3,23.26 U1.4
N2476223: length 3.8
  TOP w0.32: L31.1 22.85,24.35 22.37,23.88 21.65,23.88 20.8,23.02 U1.3
N2476600: length 5.9
  TOP w0.32: C12.1 25.83,24.36 L12.1 25.33,23.82 L11.1 24.44,22.85 22.87,22.85 22.85,22.88 22.03,22.88 21.8,22.65 U1.1
N5175910: length 0.8
  TOP w0.32: 15.67,30.38 L55.1

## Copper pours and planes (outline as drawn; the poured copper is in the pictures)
GND on TOP: 0.45,47.45 0.45,0.45 40.37,0.45 40.37,47.45 ; 6 cut-outs
GND on BOTTOM: 0.45,47.45 0.45,0.45 40.37,0.45 40.37,47.45 ; 9 cut-outs
GND on L2: 0.45,47.45 0.45,0.45 40.37,0.45 40.37,47.45
GND on L3: 0.45,47.45 0.45,0.45 40.37,0.45 40.37,47.45 ; 2 cut-outs
VDD_EB on TOP: 31.33,12.8 33,12.8 33.17,12.62 33.17,11.22 32.95,11 31.33,11 31.12,11.2 31.12,12.6
VDD_EB on BOTTOM: 32.17,12.8 35.12,12.8 35.37,12.55 35.37,11.15 35.12,10.9 32.25,10.9 32,11.15 32,12.62
VDDR on TOP: 20.72,11.6 21.5,11.6 21.5,10.58 22.73,10.58 22.73,9.95 20.72,9.95
VDDR on L3: 23.52,10.7 26.02,13.02 26.02,20.77 23.48,20.77 23.48,22.65 24.25,22.65 24.25,21.85 27.23,21.85 27.23,13.4 25.05,11.22 23.36,9.55 20.83,9.55 20.83,10.7
VDDS on TOP: 28.42,14.33 28.42,10.1 30.5,10.1 30.5,14.33
VDDS on L3: 17.2,7 15.72,8.58 15.72,14.45 15.3,14.95 12.83,14.95 12.83,15.6 13.15,15.85 15.3,15.85 15.72,16.55 15.72,20.2 13.6,20.2 13.6,21.33 15.7,21.33 15.7,26.17 20.4,26.17 20.4,25.15 16.52,25.15 16.52,9.12 17.17,8.52 19.58,8.52 19.58,15.27 24.1,15.27 24.1,18.62 25.05,18.62 25.05,12.88 24.1,12.88 24.1,13.8 20.67,13.8 20.67,9.42 23.26,9.42 24.95,11.1 28.42,11.1 28.42,14.33 30.82,14.33 30.8,7

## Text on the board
Ref Des/Silkscreen Top: Model:CC1352-P7EM-XD7793-XD24-PA9093 | Rev  :B
XSECTION_CHART: *  SURFACE - AIR 0 MM | L1: TOP CONDUCTOR - COPPER 0.035 MM | *  DIELECTRIC - FR-4 0.175 MM | L2: L2 PLANE - COPPER 0.018 MM | *  DIELECTRIC - FR-4 1.14 MM | L3: L3 PLANE - COPPER 0.018 MM | L4: BOTTOM CONDUCTOR - COPPER 0.035 MM | DESIGN CROSS SECTION CHART | ___________________________ | TOTAL THICKNESS 1.60MM +/- 0.16MM
DIMENSION: FIGURE | FINISHED_SIZE | 0.2 | 1.501 | DRILL CHART: TOP to BOTTOM | ALL UNITS ARE IN MILLIMETERS | PLATED | NON-PLATED | QTY | 370 | 25 | 4 | 399 | TOTAL HOLES:
